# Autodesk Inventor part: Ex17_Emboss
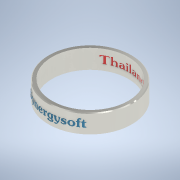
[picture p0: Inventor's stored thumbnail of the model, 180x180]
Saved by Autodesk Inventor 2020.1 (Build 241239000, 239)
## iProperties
Created: 2019-11
Part Number: Ex17_Emboss
Material: Silver
Document SubType Name: Modeling
Designer: Synergysoft Dell02
Density: 10.49 g/cm^3
Appearance: Silver
Author: Synergysoft Dell02
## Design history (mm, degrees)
sketch "Sketch1"
  geometry: C1 r 10 at (0, 0); C2 r 11 at (0, 0); 1 further point
  constraints: 2 centre point, 2 coincident
  dimensions: "d0" = 20 diameter of C1; "d1" = 22 diameter of C2
extrude "Extrusion1" new body sketch "Sketch1" distance "d2" = 5; taper "d3" = 0 deg
chamfer "Chamfer1" distance "d4" = 0.2; stored, may be unused: second distance "d5" = 2, angle "d6" = 45 deg
sketch "Sketch2"
  geometry: L1 (-9, 4)-(9, 4); L2 (9, 4)-(9, 1); L3 (9, 1)-(-9, 1); L4 (-9, 1)-(-9, 4); L5 (10, 5)-(10, 0) reference; 4 further points
  constraints: 3 midpoint, 1 horizontal alignment, 1 vertical alignment, 2 other
  dimensions: "d7" = 3 distance of L1.end L2.end; "d8" = 18 distance of L2.end L3.end
emboss "Emboss1" sketch "Sketch2" dims "d9" = 0.1, "d10" = 0
workplane "Work Plane1"
sketch "Sketch3"
  geometry: L1 (-9, 4)-(9, 4); L2 (9, 4)-(9, 1); L3 (9, 1)-(-9, 1); L4 (-9, 1)-(-9, 4); L5 (11, 0.2)-(11, 4.8) reference; 4 further points
  constraints: 3 midpoint, 1 horizontal alignment, 1 vertical alignment, 2 other
  dimensions: "d11" = 3 distance of L1.end L2.end; "d12" = 18 distance of L2.end L3.end
emboss "Emboss2" sketch "Sketch3" dims "d13" = 0.1, "d14" = 0
body "Solid1"
